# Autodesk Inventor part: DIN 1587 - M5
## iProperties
IsCustomPart: 1
Created: 2006-02
Part Number: DIN 1587 - M5
Material: Steel, Mild
Description: Hexagon Domed Cap Nuts
Document SubType Name: Modeling
Standard: DIN 1587
Designer: Andy Moles
Standards Organization: DIN
Language: en-US
Size Designation: M5
Categories: <MemberInstance><Categories><Category DisplayName="Fasteners" InternalName="e4da775c-781d-43d5-af7c-5136215cf5a6" Mnemonic="FSTN"><Category DisplayName="Nuts" I
Density: 1 g/cm^3
Author: Andy Moles
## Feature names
1. Body [Extrusion]
2. Cap [Revolution]
3. Thread [Hole]
4. Chamfer1 [Revolution]
5. Chamfer2
